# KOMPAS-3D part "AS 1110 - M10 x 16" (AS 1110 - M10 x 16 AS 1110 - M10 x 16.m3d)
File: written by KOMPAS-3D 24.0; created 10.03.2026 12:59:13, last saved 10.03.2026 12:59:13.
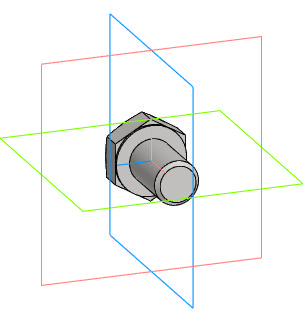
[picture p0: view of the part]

Document properties: Автор: R2D2; Полное имя файла: E:\Работа\Зайцев\BV3232P(4pc)-FP-3WL-F-ISO-H Кран шаровой DN.ru Ду15-100 Ру16\DN65\исходные материалы\AS 1110 - M10 x 16 AS 1110 - M10 x 16.m3d

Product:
- Body: Solid1  | qty 1
- Part/product: AS 1110 - M10 x 16
    Комментарий: Болты и винты   шестигранные точные   метрические ISO
    additional columns: Сталь, мягкая

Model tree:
1. Solid1  (labels: Solid1)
